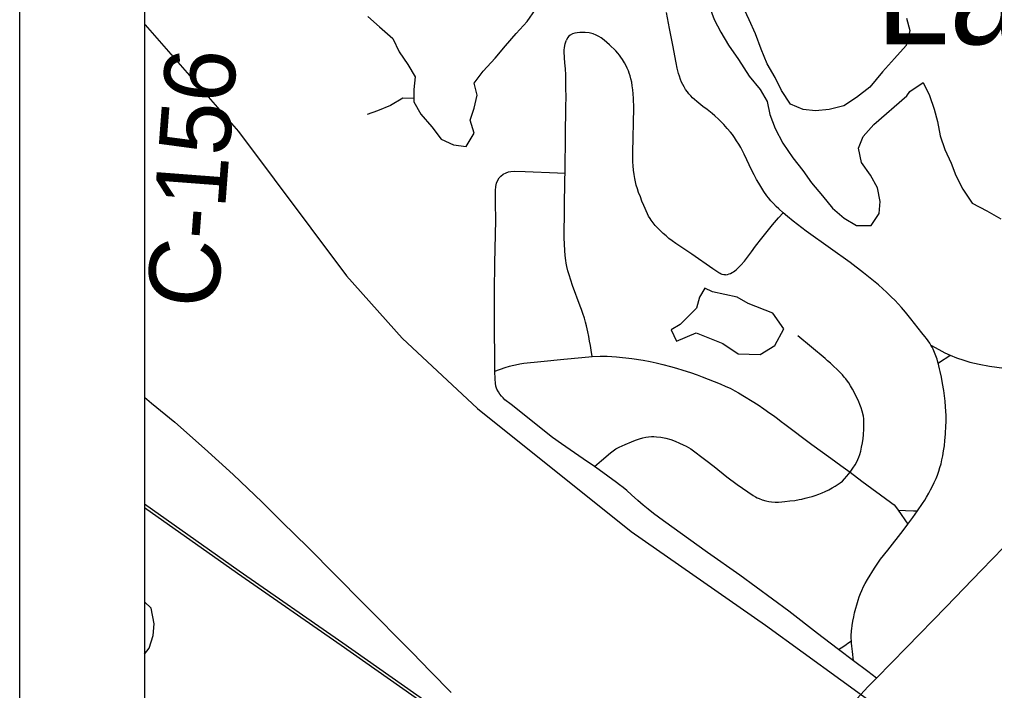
# Model space of a CAD drawing. Extents: x 0 to 34, y 0 to 22.
# Drawn here: x 2 to 2.781, y 16.587 to 17.124 of the extents above; entities that cross this region are included whole.
import ezdxf

# ---------------------------------------------------------------- set-up
doc = ezdxf.new("R2010")
doc.units = 0
for name, color, linetype in [('GM_X_Corporation', 7, 'Continuous'), ('GM_X_County_Road', 7, 'Continuous'), ('GM_X_County_Road_Text', 7, 'Continuous'), ('GM_X_Minor_Lake', 7, 'Continuous'), ('GM_X_Minor_River', 7, 'Continuous'), ('GM_X_Rail_Line', 7, 'Continuous'), ('GM_X_State_Route', 7, 'Continuous'), ('GM_X_Township_Road', 7, 'Continuous'), ('GM_X_Unincorporated_Text', 7, 'Continuous'), ('SH_Data', 7, 'Continuous')]:
    doc.layers.add(name, color=color, linetype=linetype)

msp = doc.modelspace()

# ---------------------------------------------------------------- linework, layer by layer
at = {"layer": 'GM_X_Corporation'}
msp.add_lwpolyline([(4.71799, 17.49624), (3.7119, 17.4934), (3.58006, 17.49243), (3.4708, 17.4915), (3.04564, 17.48944), (2.63524, 17.49292), (2.58119, 17.49248), (2.14492, 17.48819), (2.1, 17.48755), (2.1, 14.1), (5.03982, 14.1)], dxfattribs=at)
at = {"layer": 'GM_X_County_Road'}
msp.add_lwpolyline([(2.1, 16.82141), (2.10578, 16.8168), (2.12444, 16.80144), (2.14813, 16.78045), (2.17119, 16.75972), (2.19425, 16.73734), (2.21012, 16.72173), (2.23117, 16.7011), (2.27527, 16.65663), (2.31445, 16.61702), (2.32924, 16.60202), (2.34568, 16.58526)], dxfattribs=at)
at = {"layer": 'GM_X_Minor_Lake'}
for p, q in [((2.68415, 17.03978), (2.71046, 17.06274)), ((2.54223, 16.8927), (2.52909, 16.8797))]:
    msp.add_line(p, q, dxfattribs=at)
for points in [[(2.27887, 17.12614), (2.2884, 17.11787), (2.29907, 17.10848), (2.30407, 17.0979), (2.31097, 17.08771), (2.31672, 17.0779), (2.31567, 17.06765), (2.31574, 17.05779), (2.3215, 17.04798), (2.33028, 17.03781), (2.33755, 17.028), (2.34742, 17.02353), (2.35766, 17.02209), (2.36401, 17.03276), (2.36089, 17.04335), (2.36423, 17.05286), (2.36642, 17.06311), (2.36407, 17.07295), (2.37119, 17.08249), (2.38095, 17.0928), (2.3892, 17.10273), (2.39782, 17.11265), (2.40645, 17.1222), (2.41319, 17.13173)], [(2.55246, 17.13394), (2.55632, 17.12374), (2.5617, 17.11354), (2.56783, 17.10335), (2.57587, 17.09166), (2.5843, 17.07845), (2.59309, 17.0679), (2.59884, 17.05808), (2.60082, 17.04786), (2.60507, 17.03652), (2.61122, 17.02481), (2.61926, 17.01312), (2.62729, 17.00294), (2.63417, 16.99313), (2.64296, 16.98259), (2.65099, 16.97279), (2.66051, 16.9649), (2.6704, 16.95891), (2.68213, 16.959), (2.68849, 16.96853), (2.68917, 16.97801), (2.68719, 16.98899), (2.68143, 16.99919), (2.67417, 17.00937), (2.6718, 17.02073), (2.67551, 17.03024), (2.68415, 17.03978)], [(2.71035, 17.12493), (2.71308, 17.11509), (2.71015, 17.10293), (2.70076, 17.09262), (2.69101, 17.08193), (2.68088, 17.06971), (2.67035, 17.06129), (2.66018, 17.05477), (2.64848, 17.05164), (2.63751, 17.0508), (2.62766, 17.05186), (2.61741, 17.05595), (2.61013, 17.06689), (2.60513, 17.07747), (2.59861, 17.08842), (2.59397, 17.10014), (2.58934, 17.11224), (2.58433, 17.12357), (2.57894, 17.13491)], [(2.71046, 17.06274), (2.71308, 17.06617), (2.72362, 17.07346), (2.72863, 17.06288), (2.7325, 17.05191), (2.73522, 17.04207), (2.7372, 17.03071), (2.74107, 17.01975), (2.74608, 17.00879), (2.74994, 16.99896), (2.75533, 16.988), (2.76298, 16.97669), (2.77476, 16.97071), (2.78579, 16.96435)], [(2.52909, 16.8797), (2.52193, 16.87548), (2.52616, 16.86641), (2.54201, 16.87298), (2.56327, 16.86442), (2.57544, 16.85617), (2.59324, 16.85555), (2.60491, 16.86285), (2.612, 16.87617), (2.6032, 16.88862), (2.58346, 16.89643), (2.57471, 16.90167), (2.555, 16.90569), (2.54892, 16.90867), (2.54443, 16.90143), (2.54223, 16.8927)], [(2.1, 16.61591), (2.10382, 16.62048), (2.10714, 16.63074), (2.10782, 16.64022), (2.10546, 16.65272), (2.1, 16.65769)]]:
    msp.add_lwpolyline(points, dxfattribs=at)
at = {"layer": 'GM_X_Minor_River'}
msp.add_lwpolyline([(2.31572, 17.0605), (2.30701, 17.06076), (2.29722, 17.05499), (2.28666, 17.05074), (2.27835, 17.04764)], dxfattribs=at)
at = {"layer": 'GM_X_Rail_Line'}
for points in [[(2.1, 17.12013), (2.10054, 17.11949), (2.17525, 17.03417), (2.26176, 16.91867), (2.30634, 16.86879), (2.36664, 16.81235), (2.48988, 16.71389), (2.59739, 16.63905), (2.68785, 16.57341), (2.75866, 16.53271), (2.80848, 16.50907), (2.86749, 16.48543), (2.9619, 16.46964), (3.0612, 16.44331), (3.12429, 16.40702), (3.16858, 16.37879), (3.1981, 16.3452), (3.24371, 16.24847), (3.28931, 16.1195), (3.32016, 16.04561), (3.3376, 16.01873), (3.47588, 15.90277), (3.58094, 15.84467), (3.67315, 15.78836)], [(3.61533, 15.77286), (3.52149, 15.81821), (3.4176, 15.86849), (3.34519, 15.90428), (3.26563, 15.94335), (3.20713, 15.97485), (3.16233, 16.00062), (3.14085, 16.01371), (3.11508, 16.02946), (3.08931, 16.04583), (3.0484, 16.07303), (2.90194, 16.17571), (2.80581, 16.24219), (2.75385, 16.2786), (2.68676, 16.32544), (2.58357, 16.39765), (2.43456, 16.50196), (2.33535, 16.5711), (2.25895, 16.62459), (2.17591, 16.68237), (2.1, 16.73576)], [(3.61429, 15.77076), (3.52046, 15.81611), (3.41657, 15.86639), (3.34416, 15.90219), (3.26455, 15.94128), (3.20598, 15.97281), (3.16113, 15.99862), (3.13963, 16.01172), (3.11384, 16.02748), (3.08803, 16.04387), (3.04707, 16.07111), (2.9006, 16.1738), (2.80446, 16.24028), (2.75251, 16.27669), (2.68541, 16.32353), (2.58222, 16.39574), (2.43321, 16.50005), (2.33401, 16.56919), (2.25761, 16.62268), (2.17456, 16.68046), (2.1, 16.7329)]]:
    msp.add_lwpolyline(points, dxfattribs=at)
at = {"layer": 'GM_X_State_Route'}
msp.add_lwpolyline([(2.64413, 16.55121), (2.64749, 16.55509), (2.67948, 16.58977), (2.68624, 16.59663), (2.71032, 16.62107), (2.74219, 16.65373), (2.77029, 16.6831), (2.79668, 16.71015)], dxfattribs=at)
at = {"layer": 'GM_X_Township_Road'}
for p, q in [((2.70368, 16.73104), (2.71137, 16.71973)), ((2.66781, 16.61058), (2.65588, 16.61951))]:
    msp.add_line(p, q, dxfattribs=at)
for points in [[(2.58023, 17.01612), (2.57898, 17.01873), (2.5776, 17.02127), (2.57604, 17.02414), (2.5743, 17.0268), (2.57268, 17.02928), (2.57086, 17.03165), (2.56932, 17.03367), (2.56683, 17.03648), (2.56402, 17.03968), (2.56156, 17.04216), (2.55968, 17.04405), (2.55675, 17.04666), (2.55461, 17.04856), (2.55069, 17.05163), (2.5473, 17.05428), (2.54234, 17.05809), (2.5405, 17.05972), (2.53903, 17.06103), (2.53756, 17.06261), (2.536, 17.06427), (2.53483, 17.06584), (2.53333, 17.06784), (2.53219, 17.0698), (2.53109, 17.07169), (2.53025, 17.07358), (2.52929, 17.07576), (2.52844, 17.0784), (2.52774, 17.08058), (2.52676, 17.08488), (2.52579, 17.08913), (2.52312, 17.10321), (2.52063, 17.11663), (2.51801, 17.12935)], [(2.43697, 17.00075), (2.43727, 17.03273), (2.4376, 17.0517), (2.43766, 17.06405), (2.43761, 17.06668), (2.43756, 17.06907), (2.43752, 17.07196), (2.43747, 17.07545), (2.4374, 17.07959), (2.43717, 17.08435), (2.43674, 17.08914), (2.43638, 17.09307), (2.43624, 17.09809), (2.43629, 17.09962), (2.43645, 17.10122), (2.43679, 17.10293), (2.43708, 17.10435), (2.43762, 17.10592), (2.43812, 17.10736)], [(2.5655, 16.91954), (2.56403, 16.91949), (2.56267, 16.91967), (2.56188, 16.91991), (2.56102, 16.92037), (2.56003, 16.92103), (2.55522, 16.92436), (2.53848, 16.9359), (2.52549, 16.94459), (2.52274, 16.94661), (2.52003, 16.94859), (2.51774, 16.95054), (2.51535, 16.95257), (2.51279, 16.95511), (2.51055, 16.95733), (2.50909, 16.95902), (2.50735, 16.96102), (2.5058, 16.96324), (2.50491, 16.96451), (2.50381, 16.96649), (2.50284, 16.96823), (2.49987, 16.97502), (2.49849, 16.97852), (2.49717, 16.98186), (2.49579, 16.98534), (2.49487, 16.98825), (2.49395, 16.99118), (2.49332, 16.99389), (2.49272, 16.99654), (2.49223, 16.99981), (2.49172, 17.0032), (2.49143, 17.00679), (2.49118, 17.0099), (2.49113, 17.01319), (2.49107, 17.01724), (2.4919, 17.05307), (2.49174, 17.06059), (2.49143, 17.06421), (2.49116, 17.06747), (2.49067, 17.07077), (2.49023, 17.0737), (2.48963, 17.07623), (2.48907, 17.0786), (2.48834, 17.08079), (2.48768, 17.08276), (2.48675, 17.08484), (2.48585, 17.08682), (2.48445, 17.08919), (2.48297, 17.09174), (2.48168, 17.09356), (2.48041, 17.09536), (2.47907, 17.0969), (2.47749, 17.09871), (2.47258, 17.10355), (2.4683, 17.10729), (2.46569, 17.10913), (2.46382, 17.11018), (2.46186, 17.11128), (2.45947, 17.11227), (2.45631, 17.11304), (2.4531, 17.11335), (2.45087, 17.11337), (2.44872, 17.11336), (2.44648, 17.1131), (2.44479, 17.11278), (2.44288, 17.11223), (2.44104, 17.11129), (2.43997, 17.1104), (2.43896, 17.10907), (2.43812, 17.10736)], [(2.61143, 16.96908), (2.60808, 16.97215), (2.60597, 16.97412), (2.60368, 16.9766), (2.60172, 16.97873), (2.59984, 16.98103), (2.59855, 16.98262), (2.59619, 16.98608), (2.59434, 16.98881), (2.59201, 16.99278), (2.59022, 16.99583), (2.58829, 16.99959), (2.58651, 17.00305), (2.58023, 17.01612)], [(2.38077, 16.84237), (2.38071, 16.84563), (2.38051, 16.88303), (2.38032, 16.90628), (2.38072, 16.92867), (2.38133, 16.96311), (2.38118, 16.97707), (2.38109, 16.98705), (2.38145, 16.99025), (2.38203, 16.99278), (2.38297, 16.99526), (2.38402, 16.99695), (2.38534, 16.99838), (2.38741, 16.9999), (2.38968, 17.00111), (2.39157, 17.00179), (2.39352, 17.00219), (2.39674, 17.00235), (2.40488, 17.00202), (2.43082, 17.001), (2.43697, 17.00075)], [(2.45864, 16.85407), (2.45778, 16.85904), (2.45713, 16.86287), (2.45654, 16.86629), (2.4559, 16.86999), (2.45511, 16.87369), (2.45409, 16.87852), (2.45323, 16.88167), (2.45238, 16.88476), (2.4511, 16.88852), (2.45001, 16.89172), (2.4491, 16.89438), (2.44278, 16.91102), (2.44005, 16.91931), (2.43915, 16.92275), (2.4383, 16.92599), (2.4378, 16.92884), (2.43744, 16.93094), (2.43704, 16.93498), (2.43665, 16.93903), (2.43644, 16.9441), (2.43624, 16.94897), (2.43683, 16.99634), (2.43697, 17.00075)], [(2.5655, 16.91954), (2.56698, 16.91979), (2.56821, 16.92016), (2.56936, 16.92061), (2.57076, 16.92127), (2.57181, 16.92191), (2.57274, 16.92258), (2.57381, 16.92344), (2.57499, 16.92444), (2.57639, 16.92586), (2.57764, 16.92715), (2.58055, 16.93038), (2.58608, 16.93792), (2.58942, 16.94243), (2.59446, 16.94875), (2.60299, 16.95947), (2.60618, 16.96327), (2.60783, 16.9651), (2.61143, 16.96908)], [(2.72983, 16.86308), (2.72887, 16.86463), (2.72761, 16.86656), (2.72625, 16.86836), (2.7251, 16.86994), (2.72248, 16.87308), (2.71391, 16.88408), (2.70948, 16.88944), (2.70641, 16.89315), (2.70393, 16.89589), (2.70101, 16.8991), (2.69839, 16.90167), (2.6944, 16.90559), (2.69132, 16.90834), (2.68794, 16.91136), (2.67592, 16.92114), (2.66507, 16.92941), (2.64943, 16.94059), (2.6299, 16.95442), (2.61967, 16.9623), (2.61489, 16.96624), (2.61143, 16.96908)], [(2.66513, 16.7614), (2.66727, 16.76458), (2.66912, 16.76729), (2.67021, 16.76935), (2.67128, 16.77155), (2.67208, 16.77352), (2.67288, 16.77556), (2.67375, 16.7784), (2.67437, 16.78148), (2.67499, 16.78493), (2.67548, 16.78839), (2.67585, 16.79148), (2.67604, 16.79604), (2.67616, 16.7995), (2.6761, 16.80203), (2.67605, 16.80405), (2.67581, 16.80632), (2.67479, 16.81042), (2.67395, 16.81289), (2.67303, 16.81562), (2.67207, 16.81785), (2.67084, 16.82069), (2.66715, 16.8278), (2.66552, 16.83059), (2.66418, 16.83288), (2.66307, 16.83438), (2.66172, 16.8362), (2.66049, 16.83756), (2.65896, 16.83928), (2.65683, 16.84145), (2.6544, 16.84386), (2.65205, 16.84619), (2.64933, 16.84864), (2.64718, 16.85058), (2.6452, 16.85236), (2.62326, 16.87063)], [(2.72983, 16.86308), (2.73626, 16.85959), (2.7411, 16.85699), (2.74525, 16.85514)], [(2.73565, 16.84875), (2.73514, 16.85051), (2.73475, 16.85184), (2.73428, 16.85327), (2.73381, 16.85465), (2.73333, 16.85594), (2.7328, 16.85734), (2.73223, 16.8586), (2.73163, 16.85993), (2.73075, 16.86156), (2.72983, 16.86308)], [(2.38077, 16.84237), (2.38897, 16.84519), (2.39246, 16.84639), (2.39453, 16.84688), (2.39726, 16.84752), (2.40063, 16.84807), (2.40398, 16.84861), (2.41758, 16.84999), (2.43584, 16.85182), (2.45023, 16.85333), (2.45864, 16.85407)], [(2.45864, 16.85407), (2.46491, 16.85443), (2.47055, 16.85427), (2.47798, 16.85378), (2.49031, 16.85241), (2.49952, 16.85104), (2.50504, 16.85017), (2.50992, 16.84902), (2.5153, 16.84774), (2.52121, 16.84609), (2.52607, 16.84473), (2.53109, 16.84317), (2.53734, 16.84122), (2.54263, 16.83935), (2.54672, 16.83791), (2.56116, 16.83215), (2.56559, 16.83016), (2.5691, 16.82859), (2.57289, 16.82655), (2.57567, 16.82506), (2.59159, 16.81535), (2.59614, 16.81219), (2.60099, 16.80883), (2.60373, 16.80677), (2.6069, 16.8044), (2.60998, 16.80208), (2.61297, 16.79983), (2.63446, 16.78357), (2.64971, 16.77265), (2.65773, 16.76687), (2.66513, 16.7614)], [(2.73565, 16.84875), (2.73911, 16.85105), (2.74251, 16.85332), (2.74525, 16.85514)], [(2.74525, 16.85514), (2.75041, 16.85305), (2.75616, 16.85119), (2.76106, 16.84961), (2.76851, 16.8479), (2.77665, 16.84642), (2.78857, 16.84469), (2.79861, 16.84354), (2.80727, 16.84271), (2.81178, 16.84245), (2.81505, 16.84227), (2.81892, 16.84212)], [(2.46039, 16.76598), (2.4513, 16.77217), (2.43399, 16.78408), (2.42696, 16.78923), (2.3936, 16.81551), (2.38876, 16.81949), (2.38725, 16.82101), (2.38605, 16.82221), (2.38452, 16.8239), (2.38347, 16.8257), (2.38235, 16.82795), (2.38153, 16.83034), (2.38111, 16.83279), (2.38088, 16.83602), (2.38077, 16.84237)], [(2.71911, 16.73045), (2.72322, 16.73634), (2.72492, 16.7391), (2.72646, 16.74159), (2.7281, 16.7446), (2.7296, 16.74737), (2.73089, 16.74973), (2.73254, 16.75329), (2.734, 16.75644), (2.73506, 16.75917), (2.73623, 16.76217), (2.73714, 16.76518), (2.73801, 16.76805), (2.73872, 16.77131), (2.73945, 16.77465), (2.74002, 16.77843), (2.74065, 16.78257), (2.74104, 16.78679), (2.7415, 16.79181), (2.74158, 16.7934), (2.74175, 16.79711), (2.74204, 16.80292), (2.74199, 16.80672), (2.74194, 16.81031), (2.74166, 16.8139), (2.74133, 16.81828), (2.74077, 16.82245), (2.7402, 16.82674), (2.73915, 16.83247), (2.73823, 16.83751), (2.73727, 16.84203), (2.7368, 16.84424), (2.73631, 16.84652), (2.73589, 16.84794), (2.73565, 16.84875)], [(2.46039, 16.76598), (2.46594, 16.77078), (2.47322, 16.77701), (2.47538, 16.77867), (2.47766, 16.78009), (2.48018, 16.78148), (2.48501, 16.78367), (2.49019, 16.78582), (2.49328, 16.78705), (2.49642, 16.7881), (2.49926, 16.7889), (2.50167, 16.78946), (2.50383, 16.78976), (2.50605, 16.78995), (2.50802, 16.78995), (2.51006, 16.78989), (2.5137, 16.78951), (2.51758, 16.78877), (2.52154, 16.7876), (2.52505, 16.78636), (2.52857, 16.78482), (2.53153, 16.78346), (2.53389, 16.78226), (2.53584, 16.78111), (2.53762, 16.78006), (2.54956, 16.77121), (2.55625, 16.7659), (2.56638, 16.75784), (2.57482, 16.75157), (2.58753, 16.74282), (2.58933, 16.7418), (2.59077, 16.74099), (2.5924, 16.74029), (2.59481, 16.73925), (2.59759, 16.73845), (2.6, 16.73795), (2.60228, 16.73764), (2.60509, 16.73746), (2.60783, 16.73758), (2.61061, 16.7378), (2.613, 16.73796), (2.61679, 16.73841), (2.62093, 16.73891), (2.62427, 16.73953), (2.62641, 16.73993), (2.62912, 16.74059), (2.63227, 16.74139), (2.63474, 16.74207), (2.6372, 16.74281), (2.64012, 16.74385), (2.64285, 16.745), (2.64526, 16.74602), (2.64804, 16.74744), (2.65078, 16.74884), (2.65327, 16.75039), (2.65552, 16.7518), (2.65721, 16.75306), (2.65899, 16.75441), (2.66078, 16.75625), (2.66251, 16.75828), (2.66513, 16.7614)], [(2.65588, 16.61951), (2.65485, 16.62028), (2.639, 16.63234), (2.616, 16.65035), (2.5769, 16.67896), (2.55092, 16.69716), (2.51573, 16.72265), (2.51163, 16.72557), (2.5076, 16.72845), (2.50333, 16.73194), (2.49938, 16.73517), (2.49526, 16.73882), (2.49016, 16.74333), (2.48635, 16.7467), (2.4833, 16.74918), (2.48059, 16.75139), (2.47795, 16.75332), (2.4641, 16.76344), (2.46039, 16.76598)], [(2.66513, 16.7614), (2.67442, 16.75426), (2.69753, 16.73759), (2.6987, 16.73665), (2.70035, 16.73521), (2.7024, 16.73291), (2.70368, 16.73104)], [(2.70368, 16.73104), (2.70959, 16.73081), (2.7159, 16.73057), (2.71911, 16.73045)], [(2.71137, 16.71973), (2.71543, 16.72516), (2.71911, 16.73045)], [(2.66617, 16.62648), (2.66605, 16.62851), (2.66605, 16.62998), (2.66611, 16.63169), (2.66617, 16.63323), (2.66634, 16.6347), (2.66648, 16.63596), (2.66686, 16.63864), (2.66735, 16.64219), (2.66812, 16.64579), (2.66878, 16.6489), (2.67154, 16.65896), (2.67254, 16.66175), (2.67346, 16.66428), (2.67461, 16.66689), (2.676, 16.67002), (2.67728, 16.67239), (2.67899, 16.67555), (2.68462, 16.68455), (2.68959, 16.69173), (2.6953, 16.69914), (2.70763, 16.71473), (2.71137, 16.71973)], [(2.65588, 16.61951), (2.6601, 16.62234), (2.66194, 16.62356), (2.66345, 16.6246), (2.66617, 16.62648)], [(2.66781, 16.61058), (2.66701, 16.61784), (2.66653, 16.62232), (2.66628, 16.6245), (2.66617, 16.62648)], [(2.68624, 16.59663), (2.67945, 16.60186), (2.66781, 16.61058)]]:
    msp.add_lwpolyline(points, dxfattribs=at)
at = {"layer": 'SH_Data'}
for p, q in [((2, 21), (2, 14)), ((2.1, 20.9), (2.1, 14.1))]:
    msp.add_line(p, q, dxfattribs=at)

# ---------------------------------------------------------------- texts
at = {"layer": 'GM_X_County_Road_Text'}
msp.add_text('C-156', height=0.056818, rotation=85.64597, dxfattribs=at).set_placement((2.15851, 16.89162))
at = {"layer": 'GM_X_Unincorporated_Text'}
msp.add_text('Lakes', height=0.078977, rotation=0.00001, dxfattribs=at).set_placement((2.6859, 17.10394))

doc.saveas('drawing.dxf')
